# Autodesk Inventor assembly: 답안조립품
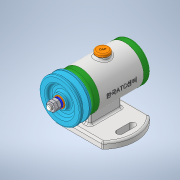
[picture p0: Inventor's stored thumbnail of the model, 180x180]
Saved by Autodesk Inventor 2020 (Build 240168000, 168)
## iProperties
Created: 2021-09
Part Number: 답안조립품
Document SubType Name: Assembly
Designer: Administrator
Author: Administrator
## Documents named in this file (14)
- C:\Users\Administrator\Desktop\710906V1018\답안조립품.iam
- C:\Users\Administrator\Desktop\710906V1018\본체.ipt
- C:\Users\Administrator\Desktop\710906V1018\축.ipt
- C:\Users\Administrator\Desktop\710906V1018\앞커버.ipt
- C:\Users\Administrator\Desktop\710906V1018\뒤커버.ipt
- C:\Users\Administrator\Desktop\710906V1018\오일 실 15x25x7.ipt
- C:\Users\Administrator\Desktop\710906V1018\베어링 15x32x9.ipt
- C:\Users\Administrator\Desktop\710906V1018\키 3x3.ipt
- C:\Users\Administrator\Desktop\710906V1018\V벨트풀리.ipt
- C:\Users\Administrator\Desktop\710906V1018\볼트 M4x12.ipt
- C:\Users\Administrator\Desktop\710906V1018\와셔 8x17.ipt
- C:\Users\Administrator\Desktop\710906V1018\스프링와셔 8.ipt
- C:\Users\Administrator\Desktop\710906V1018\너트 M8.ipt
- C:\Users\Administrator\Desktop\710906V1018\캡.ipt
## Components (1 placed, 1 different names)
1. V벨트풀리:1
